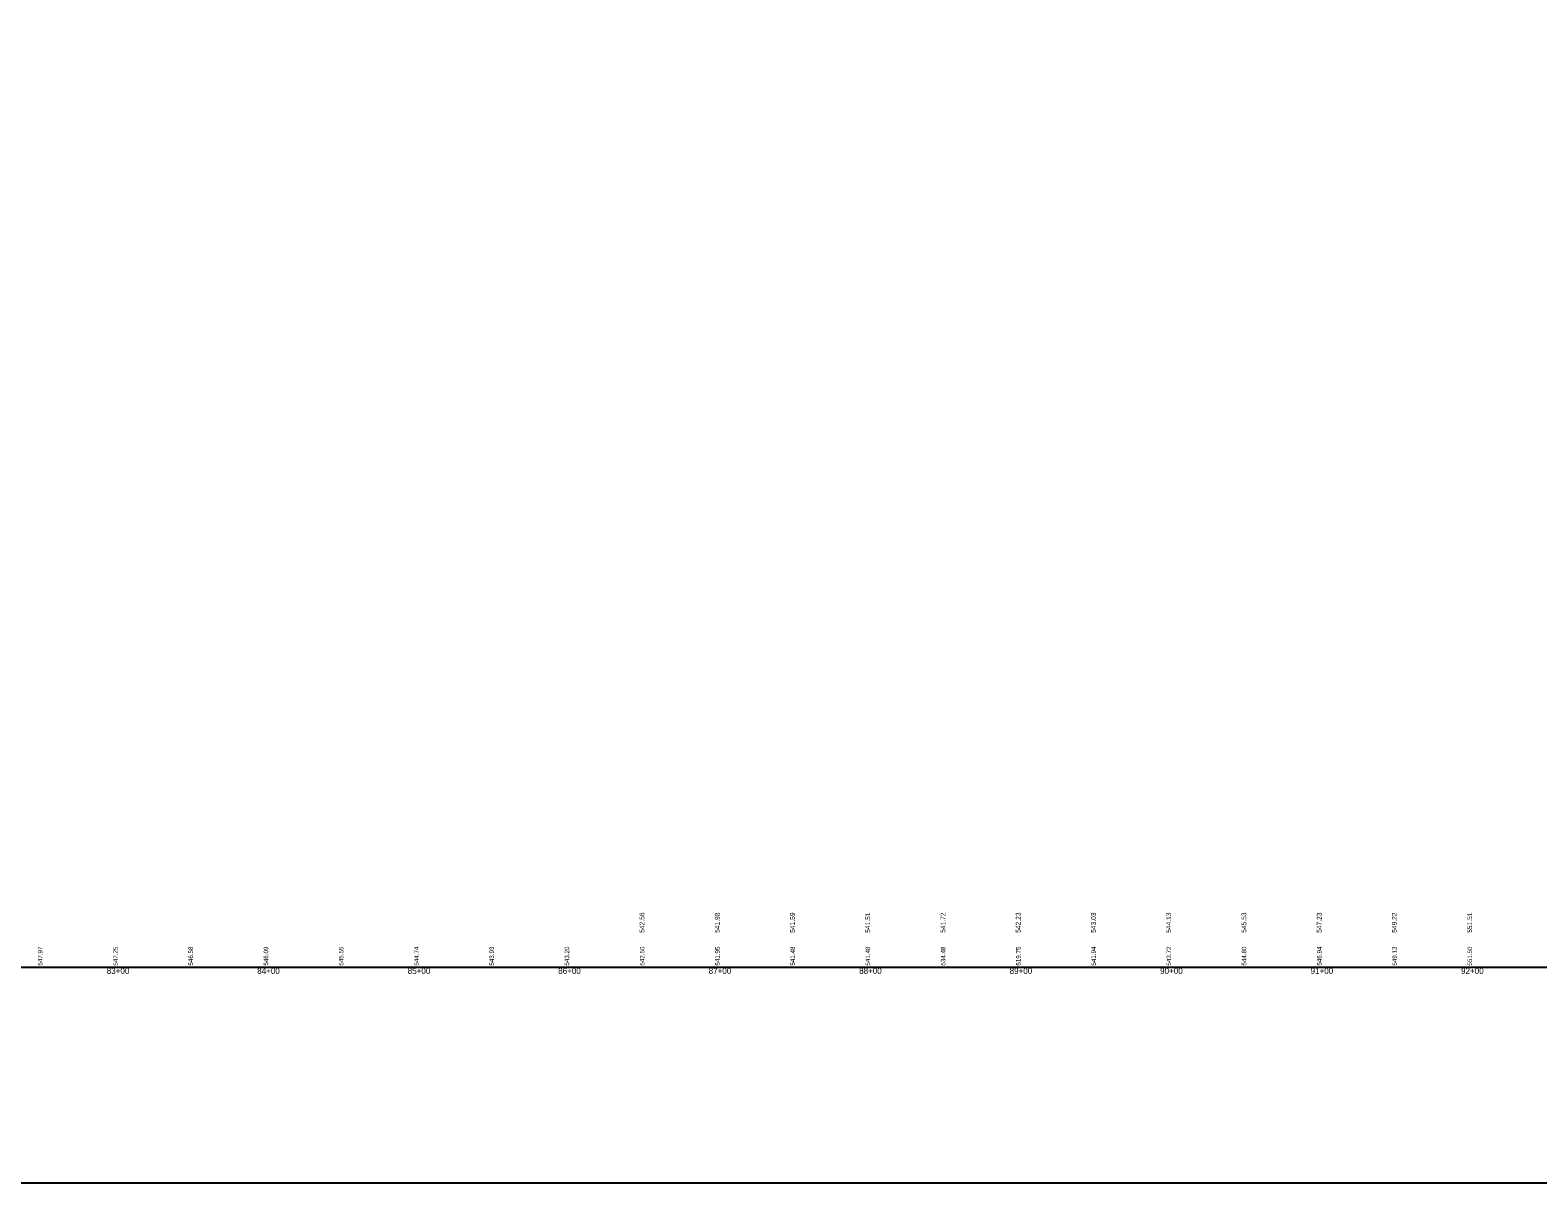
# Model space of a CAD drawing. Extents: x 1733822 to 1737718, y 1214897 to 1219897.
# Drawn here: x 1734821 to 1735823, y 1217253 to 1218020 of the extents above; entities that cross this region are included whole.
import ezdxf

# ---------------------------------------------------------------- set-up
doc = ezdxf.new("R2010")
doc.units = 0
for name, color, linetype in [('Default', 7, 'Continuous'), ('RD_DDB_StaTX', 7, 'Continuous'), ('RD_DDB_StripGrade', 7, 'Continuous'), ('RD_Sketch8', 7, 'Continuous')]:
    doc.layers.add(name, color=color, linetype=linetype)

msp = doc.modelspace()

# ---------------------------------------------------------------- linework, layer by layer
at = {"layer": 'Default'}
msp.add_line((1733879.8, 1217396.8), (1737279.8, 1217396.8), dxfattribs=at)
at = {"layer": 'RD_Sketch8'}
msp.add_lwpolyline([(1733821.6, 1217253.4), (1737421.6, 1217253.4), (1737421.6, 1219453.4), (1733821.6, 1219453.4)], close=True, dxfattribs=at)

# ---------------------------------------------------------------- texts
at = {"layer": 'RD_DDB_StaTX'}
for s, p in [('83+00', (1734872, 1217392.3)), ('83+00', (1734872, 1217392.3)), ('83+00', (1734872, 1217392.3)), ('83+00', (1734872, 1217392.3)), ('83+00', (1734872, 1217392.3)), ('84+00', (1734972, 1217392.3)), ('84+00', (1734972, 1217392.3)), ('84+00', (1734972, 1217392.3)), ('84+00', (1734972, 1217392.3)), ('84+00', (1734972, 1217392.3)), ('85+00', (1735072, 1217392.3)), ('85+00', (1735072, 1217392.3)), ('85+00', (1735072, 1217392.3)), ('85+00', (1735072, 1217392.3)), ('85+00', (1735072, 1217392.3)), ('86+00', (1735172, 1217392.3)), ('86+00', (1735172, 1217392.3)), ('86+00', (1735172, 1217392.3)), ('86+00', (1735172, 1217392.3)), ('86+00', (1735172, 1217392.3)), ('87+00', (1735272, 1217392.3)), ('87+00', (1735272, 1217392.3)), ('87+00', (1735272, 1217392.3)), ('87+00', (1735272, 1217392.3)), ('87+00', (1735272, 1217392.3)), ('88+00', (1735372, 1217392.3)), ('88+00', (1735372, 1217392.3)), ('88+00', (1735372, 1217392.3)), ('88+00', (1735372, 1217392.3)), ('88+00', (1735372, 1217392.3)), ('89+00', (1735472, 1217392.3)), ('89+00', (1735472, 1217392.3)), ('89+00', (1735472, 1217392.3)), ('89+00', (1735472, 1217392.3)), ('89+00', (1735472, 1217392.3)), ('90+00', (1735572, 1217392.3)), ('90+00', (1735572, 1217392.3)), ('90+00', (1735572, 1217392.3)), ('90+00', (1735572, 1217392.3)), ('90+00', (1735572, 1217392.3)), ('91+00', (1735672, 1217392.3)), ('91+00', (1735672, 1217392.3)), ('91+00', (1735672, 1217392.3)), ('91+00', (1735672, 1217392.3)), ('91+00', (1735672, 1217392.3)), ('92+00', (1735772, 1217392.3)), ('92+00', (1735772, 1217392.3)), ('92+00', (1735772, 1217392.3)), ('92+00', (1735772, 1217392.3)), ('92+00', (1735772, 1217392.3))]:
    msp.add_text(s, height=4, dxfattribs=at).set_placement(p)
at = {"layer": 'RD_DDB_StripGrade'}
for s, height, p in [('542.56', 3.2, (1735229.3, 1217419.6)), ('541.98', 3.2, (1735279.3, 1217419.6)), ('541.59', 3.2, (1735329.3, 1217419.6)), ('541.51', 3.2, (1735379.3, 1217419.6)), ('541.72', 3.2, (1735429.3, 1217419.6)), ('542.23', 3.2, (1735479.3, 1217419.6)), ('543.03', 3.2, (1735529.3, 1217419.6)), ('544.13', 3.2, (1735579.3, 1217419.6)), ('545.53', 3.2, (1735629.3, 1217419.6)), ('547.23', 3.2, (1735679.3, 1217419.6)), ('549.22', 3.2, (1735729.3, 1217419.6)), ('551.51', 3.2, (1735779.3, 1217419.6)), ('547.97', 3, (1734829.3, 1217397.8)), ('547.25', 3, (1734879.3, 1217397.8)), ('546.58', 3, (1734929.3, 1217397.8)), ('546.09', 3, (1734979.3, 1217397.8)), ('545.55', 3, (1735029.3, 1217397.8)), ('544.74', 3, (1735079.3, 1217397.8)), ('543.93', 3, (1735129.3, 1217397.8)), ('543.20', 3, (1735179.3, 1217397.8)), ('542.50', 3, (1735229.3, 1217397.8)), ('541.95', 3, (1735279.3, 1217397.8)), ('541.48', 3, (1735329.3, 1217397.8)), ('541.48', 3, (1735379.3, 1217397.8)), ('534.48', 3, (1735429.3, 1217397.8)), ('519.75', 3, (1735479.3, 1217397.8)), ('541.94', 3, (1735529.3, 1217397.8)), ('543.72', 3, (1735579.3, 1217397.8)), ('544.80', 3, (1735629.3, 1217397.8)), ('546.94', 3, (1735679.3, 1217397.8)), ('549.13', 3, (1735729.3, 1217397.8)), ('551.50', 3, (1735779.3, 1217397.8))]:
    msp.add_text(s, height=height, rotation=90, dxfattribs=at).set_placement(p)

doc.saveas('drawing.dxf')
